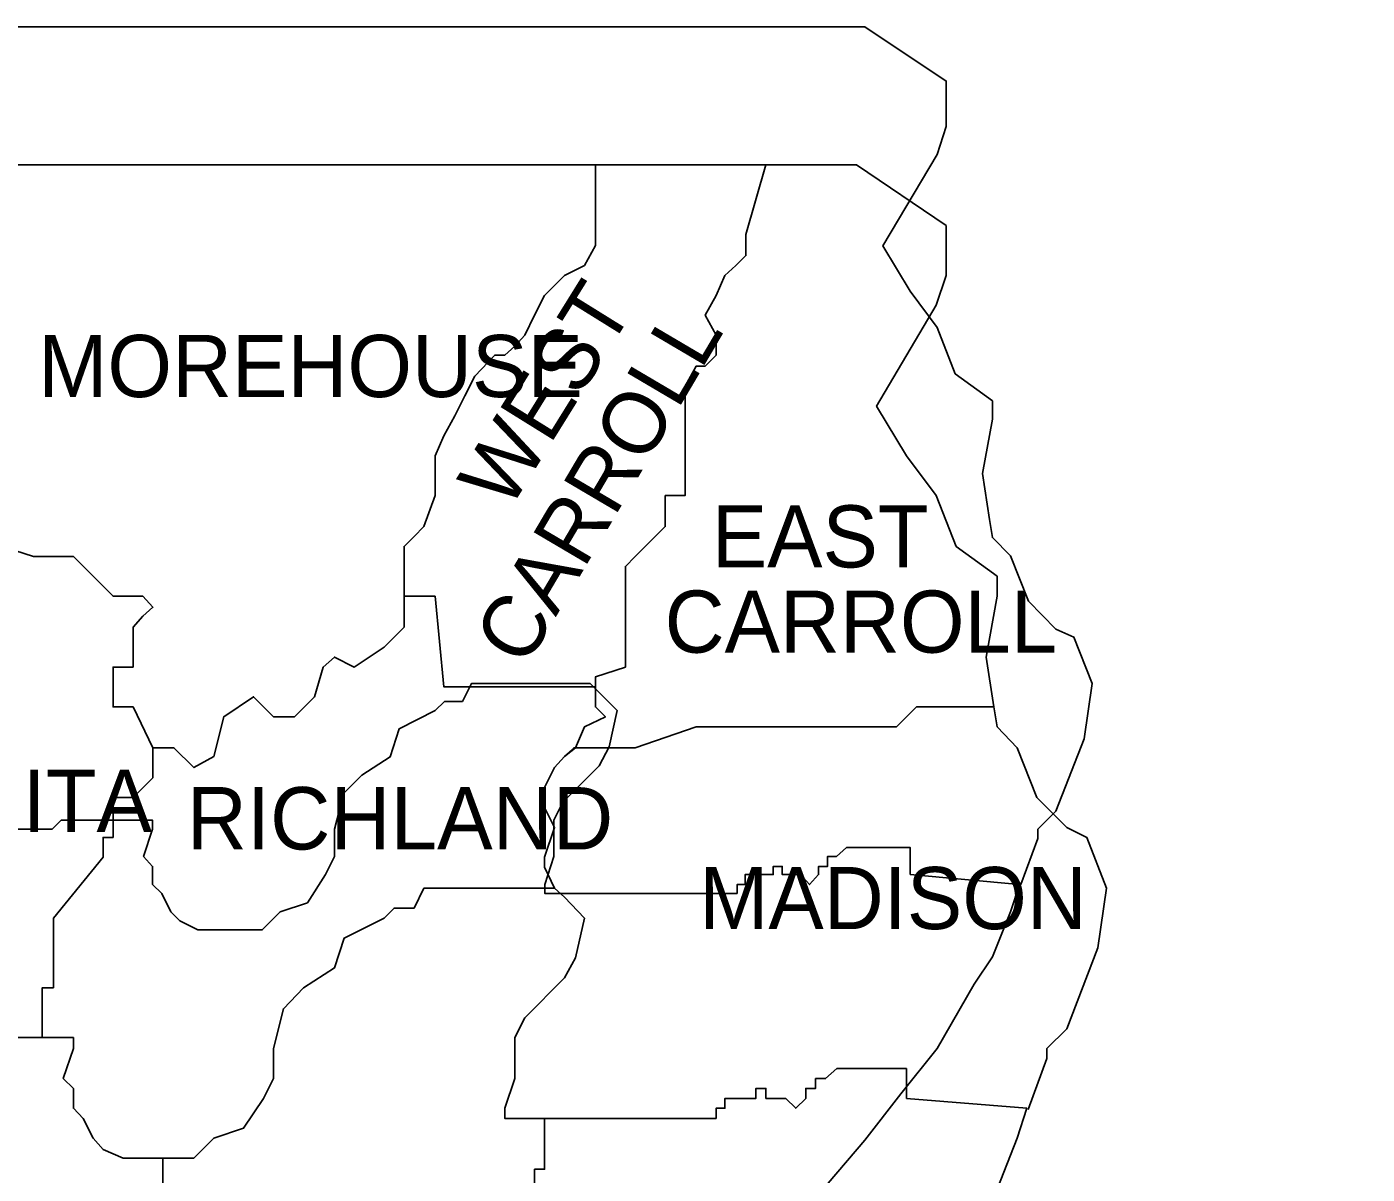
# Model space of a CAD drawing. Extents: x 0.19 to 2.82, y 0.04 to 1.79.
# Drawn here: x 2.3524 to 2.4634, y 1.6548 to 1.7498 of the extents above; entities that cross this region are included whole.
import ezdxf

# ---------------------------------------------------------------- set-up
doc = ezdxf.new("R2010")
doc.units = 0
for name, color, linetype in [('Annotation', 7, 'Continuous'), ('Dist05', 7, 'Continuous'), ('Dist58', 7, 'Continuous'), ('Standard Info', 7, 'Continuous')]:
    doc.layers.add(name, color=color, linetype=linetype)

msp = doc.modelspace()

# ---------------------------------------------------------------- linework, layer by layer
at = {"layer": 'Annotation'}
msp.add_open_spline([(2.54158, 1.67375), (2.53002, 1.63912), (2.4977, 1.61554), (2.42701, 1.62272), (2.54158, 1.67375), (2.42701, 1.62272)], degree=3, dxfattribs=at)
at = {"layer": 'Dist05'}
for p, q in [((2.3099, 1.74983), (2.35674, 1.74983)), ((2.35674, 1.74983), (2.40215, 1.74983)), ((2.40215, 1.74983), (2.41499, 1.74983)), ((2.41499, 1.74983), (2.42182, 1.74983))]:
    msp.add_line(p, q, dxfattribs=at)
for points in [[(2.42182, 1.74983), (2.42857, 1.74533), (2.42857, 1.74158), (2.42782, 1.73925), (2.42332, 1.73167), (2.42557, 1.72792), (2.42782, 1.72492), (2.42932, 1.72108), (2.4324, 1.71883), (2.4324, 1.71733), (2.43157, 1.71283), (2.43215, 1.709)], [(2.43215, 1.709), (2.4324, 1.7075), (2.4339, 1.706), (2.4354, 1.70225), (2.43765, 1.69992), (2.43915, 1.69925), (2.44065, 1.69542), (2.43999, 1.69083), (2.43765, 1.68483), (2.43615, 1.68333), (2.43615, 1.68258), (2.43474, 1.67875)], [(2.39907, 1.69542), (2.38924, 1.69542), (2.38849, 1.69392), (2.38699, 1.69392), (2.38624, 1.69317), (2.38324, 1.69167), (2.38249, 1.68933), (2.38015, 1.68783), (2.37865, 1.68633), (2.3779, 1.68333), (2.3779, 1.68108), (2.37715, 1.67958), (2.37565, 1.67725), (2.3734, 1.6765), (2.3719, 1.675), (2.36957, 1.675), (2.36807, 1.675), (2.36657, 1.675), (2.36507, 1.67575), (2.36432, 1.6765), (2.36357, 1.678), (2.36282, 1.67875), (2.36282, 1.68025), (2.36207, 1.68108), (2.36282, 1.68333), (2.36282, 1.68408), (2.36049, 1.68408)], [(2.41124, 1.678), (2.39532, 1.678), (2.39532, 1.67875), (2.39607, 1.68108), (2.39607, 1.68258), (2.39607, 1.68408), (2.39682, 1.68558), (2.39982, 1.68858), (2.40065, 1.69017), (2.40132, 1.69317), (2.39982, 1.69467), (2.39907, 1.69542)], [(2.36049, 1.68408), (2.35524, 1.68408), (2.35449, 1.68333), (2.3514, 1.68333), (2.35074, 1.68408), (2.34015, 1.68408)], [(2.42557, 1.67958), (2.42557, 1.68183), (2.42032, 1.68183), (2.41949, 1.68108), (2.41874, 1.68108), (2.41874, 1.68025), (2.41799, 1.68025), (2.41799, 1.67958), (2.41724, 1.67875), (2.41649, 1.67958), (2.41499, 1.67958), (2.41499, 1.68025), (2.41424, 1.68025), (2.41424, 1.67958), (2.4119, 1.67958), (2.4119, 1.67875), (2.41124, 1.67875), (2.41124, 1.678)], [(2.43465, 1.67875), (2.42557, 1.67958)]]:
    msp.add_lwpolyline(points, dxfattribs=at)
at = {"layer": 'Dist58'}
msp.add_line((2.43465, 1.67875), (2.43465, 1.67875), dxfattribs=at)
for points in [[(2.36049, 1.68408), (2.36282, 1.68408), (2.36282, 1.68333), (2.36207, 1.68108), (2.36282, 1.68025), (2.36282, 1.67875), (2.36357, 1.678), (2.36432, 1.6765), (2.36507, 1.67575), (2.36657, 1.675), (2.36807, 1.675), (2.36957, 1.675), (2.3719, 1.675), (2.3734, 1.6765), (2.37565, 1.67725), (2.37715, 1.67958), (2.3779, 1.68108), (2.3779, 1.68333), (2.37865, 1.68633), (2.38015, 1.68783), (2.38249, 1.68933), (2.38324, 1.69167), (2.38624, 1.69317), (2.38699, 1.69392), (2.38849, 1.69392), (2.38924, 1.69542), (2.39907, 1.69542)], [(2.39907, 1.69542), (2.39982, 1.69467), (2.40132, 1.69317), (2.40065, 1.69017), (2.39982, 1.68858), (2.39682, 1.68558), (2.39607, 1.68408), (2.39607, 1.68258), (2.39607, 1.68108), (2.39532, 1.67875), (2.39532, 1.678), (2.41124, 1.678)], [(2.34015, 1.68408), (2.35074, 1.68408), (2.3514, 1.68333), (2.35449, 1.68333), (2.35524, 1.68408), (2.36049, 1.68408)], [(2.41124, 1.678), (2.41124, 1.67875), (2.4119, 1.67875), (2.4119, 1.67958), (2.41424, 1.67958), (2.41424, 1.68025), (2.41499, 1.68025), (2.41499, 1.67958), (2.41649, 1.67958), (2.41724, 1.67875), (2.41799, 1.67958), (2.41799, 1.68025), (2.41874, 1.68025), (2.41874, 1.68108), (2.41949, 1.68108), (2.42032, 1.68183), (2.42557, 1.68183), (2.42557, 1.67958)], [(2.42557, 1.67958), (2.43465, 1.67875)], [(2.43465, 1.67875), (2.4339, 1.6765), (2.4324, 1.67275), (2.4309, 1.6705), (2.42782, 1.66517), (2.42482, 1.66142), (2.42182, 1.65758), (2.41799, 1.65308), (2.41424, 1.64933), (2.41274, 1.647), (2.40899, 1.63942)]]:
    msp.add_lwpolyline(points, dxfattribs=at)
at = {"layer": 'Standard Info'}
for p, q in [((2.34955, 1.7384), (2.39951, 1.7384)), ((2.39951, 1.7384), (2.41363, 1.7384)), ((2.41363, 1.7384), (2.42115, 1.7384)), ((2.39777, 1.69009), (2.39768, 1.69009))]:
    msp.add_line(p, q, dxfattribs=at)
for points in [[(2.38365, 1.70265), (2.38365, 1.7043), (2.38365, 1.70677), (2.38448, 1.7076), (2.3853, 1.70842), (2.38622, 1.71099), (2.38622, 1.71429), (2.38695, 1.71594), (2.38787, 1.71759), (2.3887, 1.71924), (2.38952, 1.72089), (2.39117, 1.72263), (2.392, 1.72263), (2.39282, 1.72336), (2.39365, 1.72428), (2.39447, 1.72593), (2.3953, 1.72758), (2.39695, 1.72923), (2.3986, 1.73006), (2.39951, 1.73171), (2.39951, 1.73262), (2.39951, 1.7384)], [(2.39951, 1.7384), (2.39951, 1.73262), (2.39951, 1.73171), (2.3986, 1.73006), (2.39695, 1.72923), (2.3953, 1.72758), (2.39447, 1.72593), (2.39365, 1.72428), (2.39282, 1.72336), (2.392, 1.72263), (2.39117, 1.72263), (2.38952, 1.72089), (2.3887, 1.71924), (2.38787, 1.71759), (2.38695, 1.71594), (2.38622, 1.71429), (2.38622, 1.71099), (2.3853, 1.70842), (2.38448, 1.7076), (2.38365, 1.70677), (2.38365, 1.7043), (2.38365, 1.70265)], [(2.38365, 1.70265), (2.38365, 1.7043), (2.38365, 1.70677), (2.38448, 1.7076), (2.3853, 1.70842), (2.38622, 1.71099), (2.38622, 1.71429), (2.38695, 1.71594), (2.38787, 1.71759), (2.3887, 1.71924), (2.38952, 1.72089), (2.39117, 1.72263), (2.392, 1.72263), (2.39282, 1.72336), (2.39365, 1.72428), (2.39447, 1.72593), (2.3953, 1.72758), (2.39695, 1.72923), (2.3986, 1.73006), (2.39951, 1.73171), (2.39951, 1.73262), (2.39951, 1.7384)], [(2.39795, 1.69027), (2.3986, 1.69183), (2.40034, 1.69266), (2.39951, 1.69348), (2.39951, 1.69513), (2.39951, 1.69596), (2.40199, 1.69678), (2.40199, 1.69761), (2.40199, 1.69843), (2.40199, 1.69935), (2.40199, 1.701), (2.40199, 1.70265), (2.40199, 1.70512), (2.40281, 1.70595), (2.40364, 1.70677), (2.40446, 1.7076), (2.40529, 1.70842), (2.40529, 1.71099), (2.40694, 1.71099), (2.40694, 1.72006), (2.40785, 1.72171), (2.40859, 1.72171), (2.4095, 1.72263), (2.4095, 1.72428), (2.40859, 1.72593), (2.4095, 1.72758), (2.41024, 1.72923), (2.41115, 1.73006), (2.41198, 1.73088), (2.41198, 1.73262), (2.41363, 1.7384)], [(2.41363, 1.7384), (2.41198, 1.73262), (2.41198, 1.73088), (2.41115, 1.73006), (2.41024, 1.72923), (2.4095, 1.72758), (2.40859, 1.72593), (2.4095, 1.72428), (2.4095, 1.72263), (2.40859, 1.72171), (2.40785, 1.72171), (2.40694, 1.72006), (2.40694, 1.71099), (2.40529, 1.71099), (2.40529, 1.70842), (2.40446, 1.7076), (2.40364, 1.70677), (2.40281, 1.70595), (2.40199, 1.70512), (2.40199, 1.70265), (2.40199, 1.701), (2.40199, 1.69935), (2.40199, 1.69843), (2.40199, 1.69761), (2.40199, 1.69678), (2.39951, 1.69596), (2.39951, 1.69513)], [(2.42115, 1.7384), (2.42857, 1.73336), (2.42857, 1.72923), (2.42775, 1.72676), (2.4228, 1.71841), (2.42527, 1.71429), (2.42775, 1.71099), (2.4294, 1.70677), (2.43279, 1.7043), (2.43279, 1.70265), (2.43187, 1.69761), (2.43251, 1.69348)], [(2.34974, 1.70696), (2.35295, 1.70595), (2.35625, 1.70595), (2.3579, 1.7043), (2.35955, 1.70265), (2.36202, 1.70265), (2.36285, 1.70173), (2.36202, 1.701), (2.3612, 1.70008), (2.3612, 1.69678), (2.35955, 1.69678), (2.35955, 1.69348), (2.3612, 1.69348), (2.36285, 1.69009), (2.36285, 1.68761), (2.3612, 1.68596), (2.35955, 1.68596), (2.35955, 1.68266), (2.35872, 1.68266), (2.35872, 1.68101), (2.3546, 1.67597), (2.3546, 1.6702), (2.35368, 1.6702), (2.35368, 1.66607)], [(2.36285, 1.69009), (2.3612, 1.69348), (2.35955, 1.69348), (2.35955, 1.69678), (2.3612, 1.69678), (2.3612, 1.70008), (2.36202, 1.701), (2.36285, 1.70173), (2.36202, 1.70265), (2.35955, 1.70265), (2.3579, 1.7043), (2.35625, 1.70595), (2.35295, 1.70595), (2.34974, 1.70696)], [(2.38365, 1.70265), (2.38365, 1.70008), (2.382, 1.69843), (2.37953, 1.69678), (2.37788, 1.69761), (2.37696, 1.69678), (2.37623, 1.69431), (2.37458, 1.69266), (2.37284, 1.69266), (2.37119, 1.69431), (2.36871, 1.69266), (2.36789, 1.68936), (2.36624, 1.68844), (2.36459, 1.69009), (2.36285, 1.69009)], [(2.36285, 1.69009), (2.36459, 1.69009), (2.36624, 1.68844), (2.36789, 1.68936), (2.36871, 1.69266), (2.37119, 1.69431), (2.37284, 1.69266), (2.37458, 1.69266), (2.37623, 1.69431), (2.37696, 1.69678), (2.37788, 1.69761), (2.37953, 1.69678), (2.382, 1.69843), (2.38365, 1.70008), (2.38365, 1.70265)], [(2.39951, 1.69513), (2.38695, 1.69513), (2.38622, 1.70265), (2.38365, 1.70265)], [(2.38365, 1.70265), (2.38622, 1.70265), (2.38695, 1.69513), (2.39951, 1.69513)], [(2.39951, 1.69513), (2.39951, 1.69348), (2.40034, 1.69266), (2.3986, 1.69183), (2.39786, 1.69009), (2.39695, 1.68936), (2.39612, 1.68844), (2.3953, 1.68679), (2.3953, 1.68596), (2.3953, 1.68514), (2.39612, 1.68349), (2.3953, 1.68101), (2.3953, 1.68019), (2.39612, 1.67845)], [(2.43251, 1.69348), (2.4261, 1.69348), (2.42445, 1.69183), (2.40785, 1.69183), (2.40281, 1.69009), (2.39768, 1.69009)], [(2.39768, 1.69009), (2.40281, 1.69009), (2.40785, 1.69183), (2.42445, 1.69183), (2.4261, 1.69348), (2.43251, 1.69348)], [(2.43251, 1.69348), (2.43279, 1.69183), (2.43444, 1.69009), (2.43609, 1.68596), (2.43856, 1.68349), (2.44021, 1.68266), (2.44186, 1.67845), (2.44113, 1.6735), (2.43856, 1.66681), (2.43691, 1.66516), (2.43691, 1.66433), (2.43535, 1.66011)], [(2.35368, 1.66607), (2.35368, 1.6702), (2.3546, 1.6702), (2.3546, 1.67597), (2.35872, 1.68101), (2.35872, 1.68266), (2.35955, 1.68266), (2.35955, 1.68596), (2.3612, 1.68596), (2.36285, 1.68761), (2.36285, 1.69009)], [(2.39612, 1.67845), (2.3953, 1.68019), (2.3953, 1.68101), (2.39612, 1.68349), (2.3953, 1.68514), (2.3953, 1.68596), (2.3953, 1.68679), (2.39612, 1.68844), (2.39695, 1.68936), (2.39777, 1.69009)], [(2.39612, 1.67845), (2.3853, 1.67845), (2.38448, 1.6768), (2.38283, 1.6768), (2.382, 1.67597), (2.3787, 1.67432), (2.37788, 1.67185), (2.37531, 1.6702), (2.37366, 1.66846), (2.37284, 1.66516), (2.37284, 1.66268), (2.37201, 1.66103), (2.37036, 1.65856), (2.36789, 1.65773), (2.36624, 1.65608), (2.36367, 1.65608), (2.36202, 1.65608), (2.36037, 1.65608), (2.35872, 1.65681), (2.3579, 1.65773), (2.35707, 1.65938), (2.35625, 1.66021), (2.35625, 1.66186), (2.35542, 1.66268), (2.35625, 1.66516), (2.35625, 1.66607), (2.35368, 1.66607)], [(2.36367, 1.65608), (2.36624, 1.65608), (2.36789, 1.65773), (2.37036, 1.65856), (2.37201, 1.66103), (2.37284, 1.66268), (2.37284, 1.66516), (2.37366, 1.66846), (2.37531, 1.6702), (2.37788, 1.67185), (2.3787, 1.67432), (2.382, 1.67597), (2.38283, 1.6768), (2.38448, 1.6768), (2.3853, 1.67845), (2.39612, 1.67845)], [(2.4095, 1.65938), (2.392, 1.65938), (2.392, 1.66021), (2.39282, 1.66268), (2.39282, 1.66433), (2.39282, 1.66607), (2.39365, 1.66772), (2.39695, 1.67102), (2.39786, 1.67267), (2.3986, 1.67597), (2.39695, 1.67771), (2.39612, 1.67845)], [(2.39612, 1.67845), (2.39695, 1.67771), (2.3986, 1.67597), (2.39786, 1.67267), (2.39695, 1.67102), (2.39365, 1.66772), (2.39282, 1.66607), (2.39282, 1.66433), (2.39282, 1.66268), (2.392, 1.66021), (2.392, 1.65938), (2.3953, 1.65938)], [(2.35368, 1.66607), (2.3479, 1.66607), (2.34708, 1.66516), (2.34369, 1.66516), (2.34295, 1.66607), (2.33131, 1.66607)], [(2.33131, 1.66607), (2.34295, 1.66607), (2.34369, 1.66516), (2.34708, 1.66516), (2.3479, 1.66607), (2.35625, 1.66607), (2.35625, 1.66516), (2.35542, 1.66268), (2.35625, 1.66186), (2.35625, 1.66021), (2.35707, 1.65938), (2.3579, 1.65773), (2.35872, 1.65681), (2.36037, 1.65608), (2.36202, 1.65608), (2.36367, 1.65608)], [(2.42527, 1.66103), (2.42527, 1.66351), (2.4195, 1.66351), (2.41858, 1.66268), (2.41775, 1.66268), (2.41775, 1.66186), (2.41693, 1.66186), (2.41693, 1.66103), (2.4161, 1.66021), (2.41528, 1.66103), (2.41363, 1.66103), (2.41363, 1.66186), (2.4128, 1.66186), (2.4128, 1.66103), (2.41024, 1.66103), (2.41024, 1.66021), (2.4095, 1.66021), (2.4095, 1.65938)], [(2.4095, 1.65938), (2.4095, 1.66021), (2.41024, 1.66021), (2.41024, 1.66103), (2.4128, 1.66103), (2.4128, 1.66186), (2.41363, 1.66186), (2.41363, 1.66103), (2.41528, 1.66103), (2.4161, 1.66021), (2.41693, 1.66103), (2.41693, 1.66186), (2.41775, 1.66186), (2.41775, 1.66268), (2.41858, 1.66268), (2.4195, 1.66351), (2.42527, 1.66351), (2.42527, 1.66103)], [(2.43526, 1.66021), (2.42527, 1.66103)], [(2.42527, 1.66103), (2.43526, 1.66021)], [(2.3953, 1.65938), (2.3953, 1.65516), (2.39447, 1.65516), (2.39447, 1.65021), (2.3953, 1.64939), (2.3953, 1.64774), (2.39447, 1.64774), (2.39447, 1.64352), (2.3953, 1.64187), (2.3953, 1.64022), (2.39447, 1.6394), (2.39365, 1.63857), (2.39365, 1.63692), (2.39447, 1.63518), (2.39365, 1.63353), (2.39282, 1.6328), (2.392, 1.6328), (2.39117, 1.63188), (2.38952, 1.63188), (2.38952, 1.63023)], [(2.39447, 1.65021), (2.39447, 1.65516), (2.3953, 1.65516), (2.3953, 1.65938)], [(2.3953, 1.65938), (2.4095, 1.65938)], [(2.43526, 1.66021), (2.43444, 1.65773), (2.43279, 1.65351), (2.43114, 1.65104), (2.42775, 1.64517), (2.42445, 1.64105), (2.42115, 1.63692), (2.41693, 1.63188), (2.4128, 1.62776), (2.41115, 1.62528), (2.40703, 1.61694)], [(2.36367, 1.65608), (2.36367, 1.65351), (2.36532, 1.65186), (2.36532, 1.64939), (2.36459, 1.64939), (2.36285, 1.64856), (2.36202, 1.64774), (2.36202, 1.64609), (2.36285, 1.64517), (2.36367, 1.64352), (2.36367, 1.64105), (2.36367, 1.63857), (2.36459, 1.63775)], [(2.36367, 1.65351), (2.36367, 1.65608)]]:
    msp.add_lwpolyline(points, dxfattribs=at)

# ---------------------------------------------------------------- texts
for s, rotation, p in [('WEST', 58.1411, (2.3923, 1.7096)), ('CARROLL', 59.4887, (2.39369, 1.69661))]:
    msp.add_text(s, height=0.005147, rotation=rotation, dxfattribs=at).set_placement(p)
for s, height, p in [('MOREHOUSE', 0.005147, (2.35334, 1.71915)), ('EAST', 0.005147, (2.40914, 1.70503)), ('CARROLL', 0.005146, (2.40524, 1.69797)), ('OUACHITA', 0.005147, (2.3272, 1.68312)), ('RICHLAND', 0.00517, (2.36564, 1.68166)), ('MADISON', 0.005147, (2.4081, 1.67506))]:
    msp.add_text(s, height=height, dxfattribs=at).set_placement(p)

doc.saveas('drawing.dxf')
